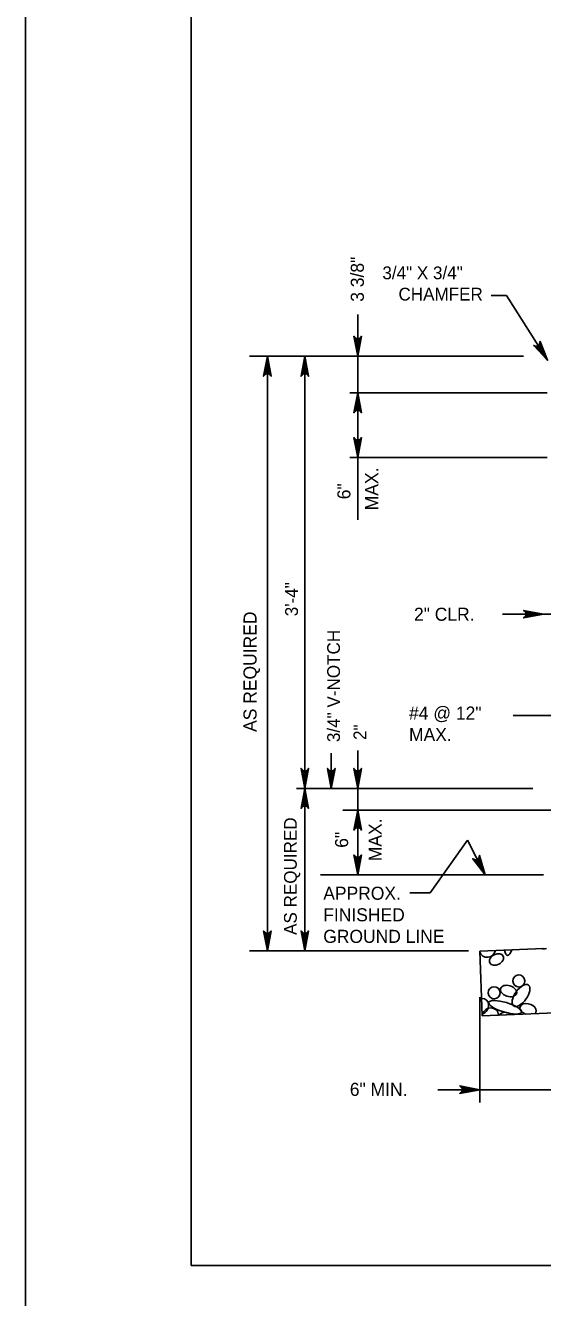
# Model space of a CAD drawing. Extents: x 638167 to 640248, y 296544 to 298920.
# Drawn here: x 638166.8 to 638288.4, y 297740 to 298039.1 of the extents above; entities that cross this region are included whole.
import ezdxf

# ---------------------------------------------------------------- set-up
doc = ezdxf.new("R2010")
doc.units = 0
doc.layers.add('1', color=7, linetype='Continuous')
doc.layers.add('PLT-BNDY', color=7, linetype='Continuous')

msp = doc.modelspace()

# ---------------------------------------------------------------- linework, layer by layer
at = {"layer": '1'}
for p, q in [((638205.78, 298311.48), (638205.78, 297747.48)), ((638276.35, 297975.58), (638279.92, 297975.58)), ((638279.92, 297975.58), (638289.6, 297960.33)), ((638244.94, 297922.81), (638244.94, 297971.11)), ((638219.51, 297961.28), (638283.94, 297961.28)), ((638223.69, 297821.5), (638223.69, 297961.28)), ((638232.52, 297821.5), (638232.52, 297961.28)), ((638243.13, 297952.71), (638289.53, 297952.71)), ((638243.13, 297937.47), (638289.53, 297937.47)), ((638279.02, 297900.66), (638304.85, 297900.66)), ((638281.53, 297876.86), (638293.73, 297876.86)), ((638238.73, 297867.99), (638238.73, 297859.68)), ((638244.94, 297839.36), (638244.94, 297868.58)), ((638230.53, 297859.68), (638286.12, 297859.68)), ((638241.42, 297854.6), (638308.85, 297854.6)), ((638261.98, 297835.14), (638270.77, 297847.49)), ((638270.77, 297847.49), (638274.96, 297839.36)), ((638236.16, 297839.36), (638288.65, 297839.36)), ((638257.17, 297835.14), (638261.98, 297835.14)), ((638219.51, 297821.5), (638270.98, 297821.5)), ((638273.64, 297821.44), (638288.65, 297822.04)), ((638273.64, 297821.44), (638274.25, 297806.21)), ((638274.25, 297806.21), (638634.6, 297820.62)), ((638273.64, 297785.85), (638273.64, 297810.61)), ((638263.78, 297788.85), (638298.47, 297788.85)), ((638205.78, 297747.48), (638991.78, 297747.48))]:
    msp.add_line(p, q, dxfattribs=at)
for points in [[(638244.94, 297961.28), (638244.06, 297965.98), (638244.18, 297965.8), (638244.31, 297965.62), (638244.47, 297965.52), (638244.62, 297965.43), (638244.78, 297965.4), (638244.94, 297965.37), (638245.1, 297965.4), (638245.25, 297965.43), (638245.41, 297965.52), (638245.57, 297965.62), (638245.69, 297965.8), (638245.82, 297965.98), (638244.94, 297961.28), (638245.69, 297965.8), (638245.57, 297965.62), (638244.94, 297961.28), (638245.41, 297965.52), (638245.25, 297965.43), (638244.94, 297961.28), (638245.1, 297965.4), (638244.94, 297965.37), (638244.94, 297961.28), (638244.78, 297965.4), (638244.62, 297965.43), (638244.94, 297961.28), (638244.47, 297965.52), (638244.31, 297965.62), (638244.94, 297961.28), (638244.18, 297965.8)], [(638289.6, 297960.33), (638286.34, 297963.82), (638286.54, 297963.74), (638286.74, 297963.65), (638286.93, 297963.66), (638287.11, 297963.66), (638287.26, 297963.72), (638287.4, 297963.79), (638287.52, 297963.89), (638287.64, 297964), (638287.72, 297964.16), (638287.81, 297964.33), (638287.82, 297964.55), (638287.83, 297964.77), (638289.6, 297960.33), (638287.82, 297964.55), (638287.81, 297964.33), (638289.6, 297960.33), (638287.72, 297964.16), (638287.64, 297964), (638289.6, 297960.33), (638287.52, 297963.89), (638287.4, 297963.79), (638289.6, 297960.33), (638287.26, 297963.72), (638287.11, 297963.66), (638289.6, 297960.33), (638286.93, 297963.66), (638286.74, 297963.65), (638289.6, 297960.33), (638286.54, 297963.74)], [(638223.69, 297961.28), (638224.58, 297956.58), (638224.45, 297956.76), (638224.32, 297956.94), (638224.17, 297957.04), (638224.01, 297957.13), (638223.85, 297957.16), (638223.69, 297957.18), (638223.54, 297957.16), (638223.38, 297957.13), (638223.22, 297957.04), (638223.06, 297956.94), (638222.94, 297956.76), (638222.81, 297956.58), (638223.69, 297961.28), (638222.94, 297956.76), (638223.06, 297956.94), (638223.69, 297961.28), (638223.22, 297957.04), (638223.38, 297957.13), (638223.69, 297961.28), (638223.54, 297957.16), (638223.69, 297957.18), (638223.69, 297961.28), (638223.85, 297957.16), (638224.01, 297957.13), (638223.69, 297961.28), (638224.17, 297957.04), (638224.32, 297956.94), (638223.69, 297961.28), (638224.45, 297956.76)], [(638232.52, 297961.28), (638233.4, 297956.58), (638233.28, 297956.76), (638233.15, 297956.94), (638232.99, 297957.04), (638232.84, 297957.13), (638232.68, 297957.16), (638232.52, 297957.18), (638232.36, 297957.16), (638232.21, 297957.13), (638232.05, 297957.04), (638231.89, 297956.94), (638231.77, 297956.76), (638231.64, 297956.58), (638232.52, 297961.28), (638231.77, 297956.76), (638231.89, 297956.94), (638232.52, 297961.28), (638232.05, 297957.04), (638232.21, 297957.13), (638232.52, 297961.28), (638232.36, 297957.16), (638232.52, 297957.18), (638232.52, 297961.28), (638232.68, 297957.16), (638232.84, 297957.13), (638232.52, 297961.28), (638232.99, 297957.04), (638233.15, 297956.94), (638232.52, 297961.28), (638233.28, 297956.76)], [(638244.94, 297952.71), (638245.82, 297948.01), (638245.69, 297948.19), (638245.57, 297948.37), (638245.41, 297948.46), (638245.25, 297948.56), (638245.1, 297948.58), (638244.94, 297948.61), (638244.78, 297948.58), (638244.62, 297948.56), (638244.47, 297948.46), (638244.31, 297948.37), (638244.18, 297948.19), (638244.06, 297948.01), (638244.94, 297952.71), (638244.18, 297948.19), (638244.31, 297948.37), (638244.94, 297952.71), (638244.47, 297948.46), (638244.62, 297948.56), (638244.94, 297952.71), (638244.78, 297948.58), (638244.94, 297948.61), (638244.94, 297952.71), (638245.1, 297948.58), (638245.25, 297948.56), (638244.94, 297952.71), (638245.41, 297948.46), (638245.57, 297948.37), (638244.94, 297952.71), (638245.69, 297948.19)], [(638244.94, 297937.47), (638244.06, 297942.16), (638244.18, 297941.98), (638244.31, 297941.8), (638244.47, 297941.71), (638244.62, 297941.61), (638244.78, 297941.59), (638244.94, 297941.56), (638245.1, 297941.59), (638245.25, 297941.61), (638245.41, 297941.71), (638245.57, 297941.8), (638245.69, 297941.98), (638245.82, 297942.16), (638244.94, 297937.47), (638245.69, 297941.98), (638245.57, 297941.8), (638244.94, 297937.47), (638245.41, 297941.71), (638245.25, 297941.61), (638244.94, 297937.47), (638245.1, 297941.59), (638244.94, 297941.56), (638244.94, 297937.47), (638244.78, 297941.59), (638244.62, 297941.61), (638244.94, 297937.47), (638244.47, 297941.71), (638244.31, 297941.8), (638244.94, 297937.47), (638244.18, 297941.98)], [(638288.65, 297900.66), (638283.95, 297899.78), (638284.13, 297899.91), (638284.31, 297900.03), (638284.4, 297900.19), (638284.5, 297900.35), (638284.52, 297900.51), (638284.55, 297900.66), (638284.52, 297900.82), (638284.5, 297900.98), (638284.4, 297901.14), (638284.31, 297901.29), (638284.13, 297901.42), (638283.95, 297901.54), (638288.65, 297900.66), (638284.13, 297901.42), (638284.31, 297901.29), (638288.65, 297900.66), (638284.4, 297901.14), (638284.5, 297900.98), (638288.65, 297900.66), (638284.52, 297900.82), (638284.55, 297900.66), (638288.65, 297900.66), (638284.52, 297900.51), (638284.5, 297900.35), (638288.65, 297900.66), (638284.4, 297900.19), (638284.31, 297900.03), (638288.65, 297900.66), (638284.13, 297899.91)], [(638232.52, 297859.68), (638231.64, 297864.38), (638231.77, 297864.2), (638231.89, 297864.02), (638232.05, 297863.92), (638232.21, 297863.83), (638232.36, 297863.8), (638232.52, 297863.77), (638232.68, 297863.8), (638232.84, 297863.83), (638232.99, 297863.92), (638233.15, 297864.02), (638233.28, 297864.2), (638233.4, 297864.38), (638232.52, 297859.68), (638233.28, 297864.2), (638233.15, 297864.02), (638232.52, 297859.68), (638232.99, 297863.92), (638232.84, 297863.83), (638232.52, 297859.68), (638232.68, 297863.8), (638232.52, 297863.77), (638232.52, 297859.68), (638232.36, 297863.8), (638232.21, 297863.83), (638232.52, 297859.68), (638232.05, 297863.92), (638231.89, 297864.02), (638232.52, 297859.68), (638231.77, 297864.2)], [(638238.73, 297859.68), (638237.85, 297864.38), (638237.98, 297864.2), (638238.1, 297864.02), (638238.26, 297863.92), (638238.42, 297863.83), (638238.57, 297863.8), (638238.73, 297863.77), (638238.89, 297863.8), (638239.05, 297863.83), (638239.2, 297863.92), (638239.36, 297864.02), (638239.49, 297864.2), (638239.61, 297864.38), (638238.73, 297859.68), (638239.49, 297864.2), (638239.36, 297864.02), (638238.73, 297859.68), (638239.2, 297863.92), (638239.05, 297863.83), (638238.73, 297859.68), (638238.89, 297863.8), (638238.73, 297863.77), (638238.73, 297859.68), (638238.57, 297863.8), (638238.42, 297863.83), (638238.73, 297859.68), (638238.26, 297863.92), (638238.1, 297864.02), (638238.73, 297859.68), (638237.98, 297864.2)], [(638244.94, 297859.68), (638244.06, 297864.38), (638244.18, 297864.2), (638244.31, 297864.02), (638244.47, 297863.92), (638244.62, 297863.83), (638244.78, 297863.8), (638244.94, 297863.77), (638245.1, 297863.8), (638245.25, 297863.83), (638245.41, 297863.92), (638245.57, 297864.02), (638245.69, 297864.2), (638245.82, 297864.38), (638244.94, 297859.68), (638245.69, 297864.2), (638245.57, 297864.02), (638244.94, 297859.68), (638245.41, 297863.92), (638245.25, 297863.83), (638244.94, 297859.68), (638245.1, 297863.8), (638244.94, 297863.77), (638244.94, 297859.68), (638244.78, 297863.8), (638244.62, 297863.83), (638244.94, 297859.68), (638244.47, 297863.92), (638244.31, 297864.02), (638244.94, 297859.68), (638244.18, 297864.2)], [(638232.52, 297859.68), (638233.4, 297854.98), (638233.28, 297855.16), (638233.15, 297855.34), (638232.99, 297855.44), (638232.84, 297855.53), (638232.68, 297855.56), (638232.52, 297855.58), (638232.36, 297855.56), (638232.21, 297855.53), (638232.05, 297855.44), (638231.89, 297855.34), (638231.77, 297855.16), (638231.64, 297854.98), (638232.52, 297859.68), (638231.77, 297855.16), (638231.89, 297855.34), (638232.52, 297859.68), (638232.05, 297855.44), (638232.21, 297855.53), (638232.52, 297859.68), (638232.36, 297855.56), (638232.52, 297855.58), (638232.52, 297859.68), (638232.68, 297855.56), (638232.84, 297855.53), (638232.52, 297859.68), (638232.99, 297855.44), (638233.15, 297855.34), (638232.52, 297859.68), (638233.28, 297855.16)], [(638244.94, 297854.6), (638245.82, 297849.9), (638245.69, 297850.08), (638245.57, 297850.26), (638245.41, 297850.36), (638245.25, 297850.45), (638245.1, 297850.48), (638244.94, 297850.5), (638244.78, 297850.48), (638244.62, 297850.45), (638244.47, 297850.36), (638244.31, 297850.26), (638244.18, 297850.08), (638244.06, 297849.9), (638244.94, 297854.6), (638244.18, 297850.08), (638244.31, 297850.26), (638244.94, 297854.6), (638244.47, 297850.36), (638244.62, 297850.45), (638244.94, 297854.6), (638244.78, 297850.48), (638244.94, 297850.5), (638244.94, 297854.6), (638245.1, 297850.48), (638245.25, 297850.45), (638244.94, 297854.6), (638245.41, 297850.36), (638245.57, 297850.26), (638244.94, 297854.6), (638245.69, 297850.08)], [(638244.94, 297839.36), (638244.06, 297844.06), (638244.18, 297843.88), (638244.31, 297843.7), (638244.47, 297843.6), (638244.62, 297843.51), (638244.78, 297843.48), (638244.94, 297843.45), (638245.1, 297843.48), (638245.25, 297843.51), (638245.41, 297843.6), (638245.57, 297843.7), (638245.69, 297843.88), (638245.82, 297844.06), (638244.94, 297839.36), (638245.69, 297843.88), (638245.57, 297843.7), (638244.94, 297839.36), (638245.41, 297843.6), (638245.25, 297843.51), (638244.94, 297839.36), (638245.1, 297843.48), (638244.94, 297843.45), (638244.94, 297839.36), (638244.78, 297843.48), (638244.62, 297843.51), (638244.94, 297839.36), (638244.47, 297843.6), (638244.31, 297843.7), (638244.94, 297839.36), (638244.18, 297843.88)], [(638274.96, 297839.36), (638272.02, 297843.13), (638272.22, 297843.03), (638272.41, 297842.93), (638272.6, 297842.91), (638272.78, 297842.9), (638272.93, 297842.95), (638273.08, 297843), (638273.21, 297843.1), (638273.34, 297843.19), (638273.44, 297843.35), (638273.53, 297843.5), (638273.56, 297843.72), (638273.59, 297843.94), (638274.96, 297839.36), (638273.56, 297843.72), (638273.53, 297843.5), (638274.96, 297839.36), (638273.44, 297843.35), (638273.34, 297843.19), (638274.96, 297839.36), (638273.21, 297843.1), (638273.08, 297843), (638274.96, 297839.36), (638272.93, 297842.95), (638272.78, 297842.9), (638274.96, 297839.36), (638272.6, 297842.91), (638272.41, 297842.93), (638274.96, 297839.36), (638272.22, 297843.03)], [(638223.69, 297821.5), (638222.81, 297826.19), (638222.94, 297826.01), (638223.06, 297825.83), (638223.22, 297825.74), (638223.38, 297825.65), (638223.54, 297825.62), (638223.69, 297825.59), (638223.85, 297825.62), (638224.01, 297825.65), (638224.17, 297825.74), (638224.32, 297825.83), (638224.45, 297826.01), (638224.58, 297826.19), (638223.69, 297821.5), (638224.45, 297826.01), (638224.32, 297825.83), (638223.69, 297821.5), (638224.17, 297825.74), (638224.01, 297825.65), (638223.69, 297821.5), (638223.85, 297825.62), (638223.69, 297825.59), (638223.69, 297821.5), (638223.54, 297825.62), (638223.38, 297825.65), (638223.69, 297821.5), (638223.22, 297825.74), (638223.06, 297825.83), (638223.69, 297821.5), (638222.94, 297826.01)], [(638232.52, 297821.5), (638231.64, 297826.19), (638231.77, 297826.01), (638231.89, 297825.83), (638232.05, 297825.74), (638232.21, 297825.65), (638232.36, 297825.62), (638232.52, 297825.59), (638232.68, 297825.62), (638232.84, 297825.65), (638232.99, 297825.74), (638233.15, 297825.83), (638233.28, 297826.01), (638233.4, 297826.19), (638232.52, 297821.5), (638233.28, 297826.01), (638233.15, 297825.83), (638232.52, 297821.5), (638232.99, 297825.74), (638232.84, 297825.65), (638232.52, 297821.5), (638232.68, 297825.62), (638232.52, 297825.59), (638232.52, 297821.5), (638232.36, 297825.62), (638232.21, 297825.65), (638232.52, 297821.5), (638232.05, 297825.74), (638231.89, 297825.83), (638232.52, 297821.5), (638231.77, 297826.01)], [(638273.64, 297788.85), (638268.95, 297787.97), (638269.13, 297788.1), (638269.31, 297788.22), (638269.4, 297788.38), (638269.5, 297788.54), (638269.52, 297788.69), (638269.55, 297788.85), (638269.52, 297789.01), (638269.5, 297789.17), (638269.4, 297789.32), (638269.31, 297789.48), (638269.13, 297789.61), (638268.95, 297789.73), (638273.64, 297788.85), (638269.13, 297789.61), (638269.31, 297789.48), (638273.64, 297788.85), (638269.4, 297789.32), (638269.5, 297789.17), (638273.64, 297788.85), (638269.52, 297789.01), (638269.55, 297788.85), (638273.64, 297788.85), (638269.52, 297788.69), (638269.5, 297788.54), (638273.64, 297788.85), (638269.4, 297788.38), (638269.31, 297788.22), (638273.64, 297788.85), (638269.13, 297788.1)]]:
    msp.add_lwpolyline(points, dxfattribs=at)
for centre, major_axis, ratio, start_param, end_param in [((638275.48, 297821.8), (-1.75, -0.78), 0.948581, 6.161897, 8.868889), ((638280.62, 297824.46), (0.45, 4.03), 0.282192, 2.36721, 4.002176), ((638288.95, 297823.85), (1.29, 1.57), 0.844245, 3.456732, 4.114107), ((638273.9, 297808.4), (1.29, 1.57), 0.844245, 4.098637, 6.948537), ((638276.17, 297806.24), (-1.75, -0.78), 0.948581, 2.768835, 5.857924), ((638279.59, 297805.21), (-1.75, -0.78), 0.948581, 3.464469, 5.16229), ((638285.02, 297807.76), (1.88, -0.58), 0.646802, 5.825434, 10.881517)]:
    msp.add_ellipse(centre, major_axis=major_axis, ratio=ratio, start_param=start_param, end_param=end_param, dxfattribs=at)
for centre, major_axis, ratio in [((638277.6, 297819.46), (1.59, 0.79), 0.687276), ((638282.83, 297814.41), (-0.06, 1.43), 0.982495), ((638277.06, 297811.63), (-0.06, 1.43), 0.982495), ((638280.42, 297812.04), (1.88, -0.58), 0.646802), ((638283.36, 297810.99), (-1.76, -2.44), 0.479042), ((638279.63, 297808.22), (3.89, -1.14), 0.282192)]:
    msp.add_ellipse(centre, major_axis=major_axis, ratio=ratio, dxfattribs=at)
at = {"layer": 'PLT-BNDY'}
msp.add_lwpolyline([(638166.78, 298326.48), (639007.78, 298326.48), (639007.78, 297732.48), (638166.78, 297732.48)], close=True, dxfattribs=at)

# ---------------------------------------------------------------- texts
at = {"layer": '1'}
for s, height, p in [('3 3/8"', 3.072, (638246.39, 297974.09)), ('MAX.', 3.072, (638249.77, 297925.07)), ('6"', 3.072, (638243.23, 297927.66)), ('3\'-4"', 3, (638230.88, 297900.16)), ('AS REQUIRED', 3.072, (638221.15, 297872.96)), ('3/4" V-NOTCH', 3, (638240.77, 297870.57)), ('2"', 3, (638246.96, 297871.07)), ('AS REQUIRED', 3, (638230.61, 297825.23)), ('MAX.', 3.072, (638250.58, 297842.56)), ('6"', 3.072, (638242.69, 297845.72))]:
    msp.add_text(s, height=height, rotation=90, dxfattribs=at).set_placement(p)
for s, height, p in [(' 3/4" X 3/4"', 3, (638249.63, 297979.39)), ('CHAMFER', 3, (638254.54, 297974.39)), ('2" CLR.', 3.072, (638258.19, 297899.09)), ('#4 @ 12"', 3.072, (638257.02, 297875.86)), ('MAX.', 3.072, (638257.02, 297870.79)), ('APPROX.', 3.072, (638236.84, 297833.5)), ('FINISHED', 3.072, (638236.84, 297828.43)), ('GROUND LINE', 3.072, (638236.84, 297823.36)), ('6" MIN.', 3.072, (638243.09, 297787.39))]:
    msp.add_text(s, height=height, dxfattribs=at).set_placement(p)

doc.saveas('drawing.dxf')
